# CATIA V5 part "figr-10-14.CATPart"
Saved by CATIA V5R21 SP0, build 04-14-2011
Part number: Part1
Bounding box of the stored display mesh (mm): x -59.023 to 59.085, y -59.069 to 29.542, z 0 to 150
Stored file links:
  D:\CATIA V5R21 E-RESOURCES\CATIA-V5R21\catia-v5r21-prt\c10-catia-v5r20-prt\c10-catia-v5r21-figr-10-14.CATPart
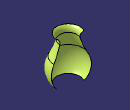
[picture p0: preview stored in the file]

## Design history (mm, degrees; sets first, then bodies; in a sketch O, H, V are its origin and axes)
Set1
  Sketch1 on yz-plane, origin (0, 0, 0), H (0, 1, 0), V (0, 0, 1)
    arc A1 centre (219.5293, 176.8574) radius 194.8379 from (50.3627, 80.1907) to (30.3627, 130.1907) cw
    arc A2 centre (-7.8186, 46.9443) radius 67.0103 from (50.3627, 80.1907) to (40, 0) cw
    arc A3 centre (47.0688, 134.312) radius 17.207 from (30.3627, 130.1907) to (40, 150) cw
    axis line L1 (0, 156.5671) -> (0, -24.1442)
    vertical: L1 V
  Revol1: Element1 Sketch1, Angle1 -60
Body1 (main body)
